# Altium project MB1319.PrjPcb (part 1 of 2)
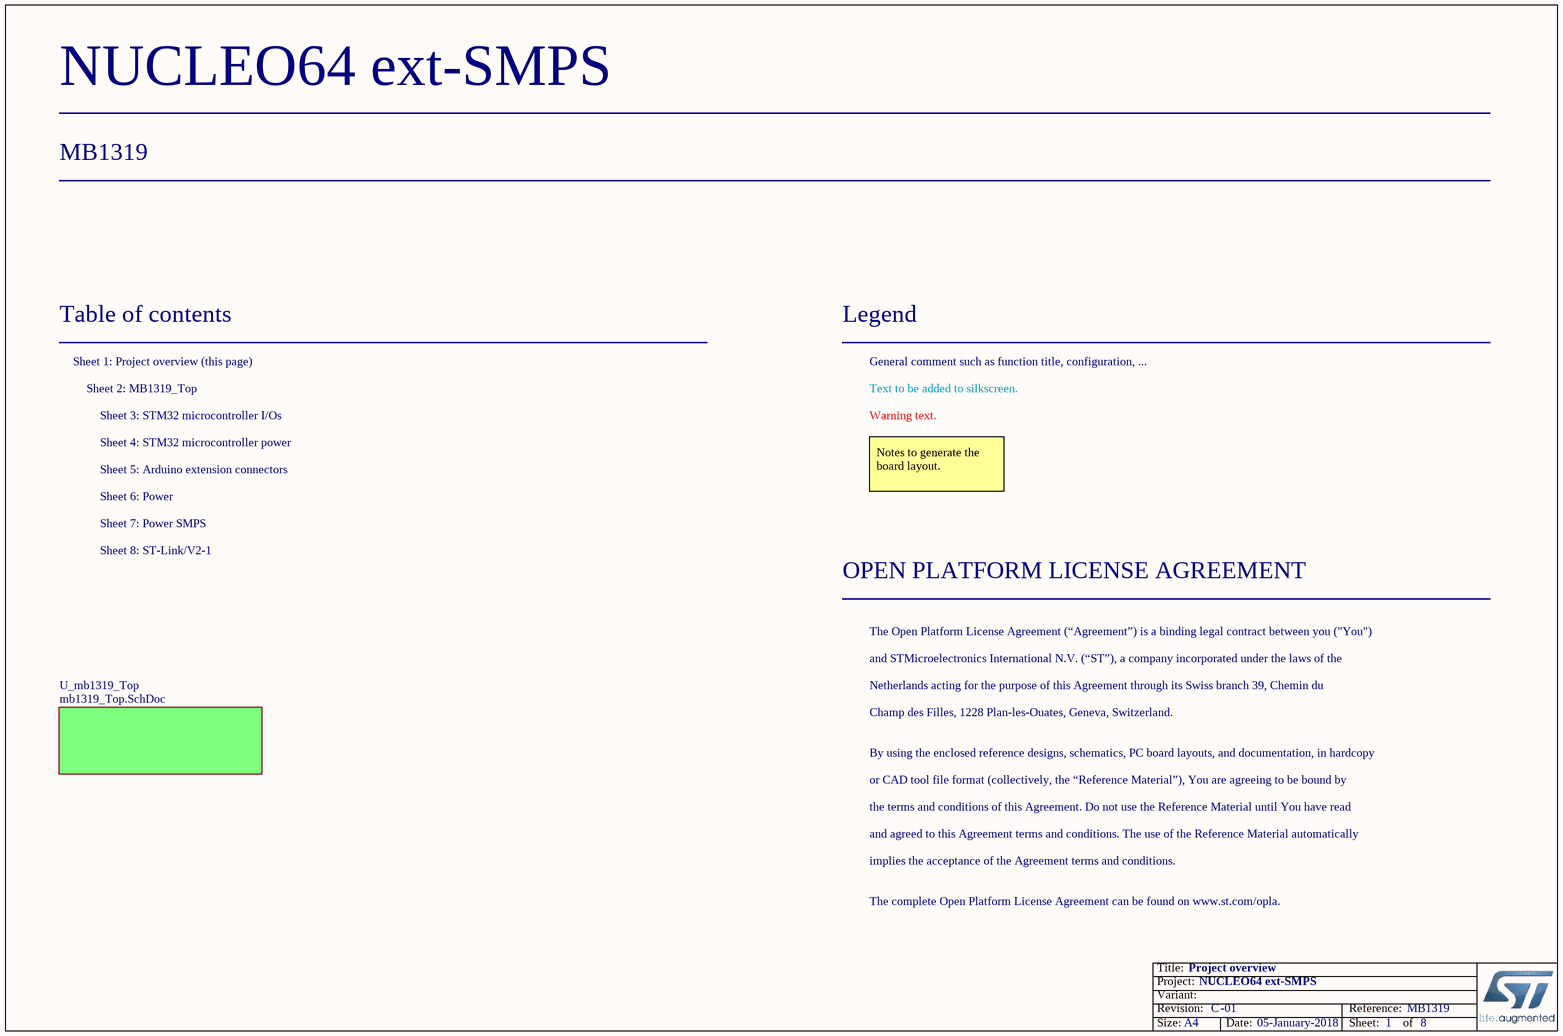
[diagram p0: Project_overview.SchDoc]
Board_Assembly_Revision: 01; Board_Document_Date: 05-January-2018; Board_Name: NUCLEO64 ext-SMPS; Board_PCB_Revision: C; Board_Reference: MB1319
8 sheets, 265 parts. Net scope: flat (ports and power ports of the same name join across sheets).
Board file: MB1319.PcbDoc
Sheets:
  Project_overview.SchDoc
    U_mb1319_Top = MB1319_Top.SchDoc
      U_STM32_microcontroller_IOs = STM32_microcontroller_IOs.SchDoc
      U_STM32_microcontroller_power = STM32_microcontroller_power.SchDoc
      U_Arduino_extension_connectors = Arduino_extension_connectors.SchDoc
      U_Power = Power.SchDoc
      U_Power SMPS = Power SMPS.SchDoc
      U_ST_LINK_V2-1 = ST_LINK_V2-1.SchDoc

## Sheet Project_overview.SchDoc: Project overview
size A4; Date: Not used; ApprovedBy: Not used; CheckedBy: Not used; Author: Not used; CompanyName: STMicroelectronics; DrawnBy: Not used; Engineer: Not used; Organization: Not used; Address1: Not used; Address2: Not used; Address3: Not used; Address4: Not used; DocumentNumber: 1; Revision: Not used; SheetNumber: 1; SheetTotal: 8

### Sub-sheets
U_mb1319_Top = mb1319_Top.SchDoc: no entries

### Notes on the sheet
- Table of contents
- Sheet 1: Project overview (this page)
- Legend
- General comment such as function title, configuration, ...
- Sheet 2: MB1319_Top
- Sheet 4: STM32 microcontroller power
- Sheet 3: STM32 microcontroller I/Os
- Text to be added to silkscreen.
- Warning text.
- Sheet 6: Power
- Sheet 5: Arduino extension connectors
- Notes to generate the board layout.
- Sheet 8: ST-Link/V2-1
- Sheet 7: Power SMPS
- OPEN PLATFORM LICENSE AGREEMENT
- The Open Platform License Agreement (“Agreement”) is a binding legal contract between you ("You")
- and STMicroelectronics International N.V. (“ST”), a company incorporated under the laws of the
- Netherlands acting for the purpose of this Agreement through its Swiss branch 39, Chemin du
- Champ des Filles, 1228 Plan-les-Ouates, Geneva, Switzerland.
- By using the enclosed reference designs, schematics, PC board layouts, and documentation, in hardcopy
- or CAD tool file format (collectively, the “Reference Material”), You are agreeing to be bound by
- the terms and conditions of this Agreement. Do not use the Reference Material until You have read
- and agreed to this Agreement terms and conditions. The use of the Reference Material automatically
- implies the acceptance of the Agreement terms and conditions.
- The complete Open Platform License Agreement can be found on www.st.com/opla.

## Sheet MB1319_Top.SchDoc: mb1319 Top: hierarchical view
size A4; Date: Not used; ApprovedBy: Not used; CheckedBy: Not used; Author: Not used; CompanyName: STMicroelectronics; DrawnBy: Not used; Engineer: Not used; Organization: Not used; Address1: Not used; Address2: Not used; Address3: Not used; Address4: Not used; DocumentNumber: 2; Revision: A-01-P3; SheetNumber: 2; SheetTotal: 8
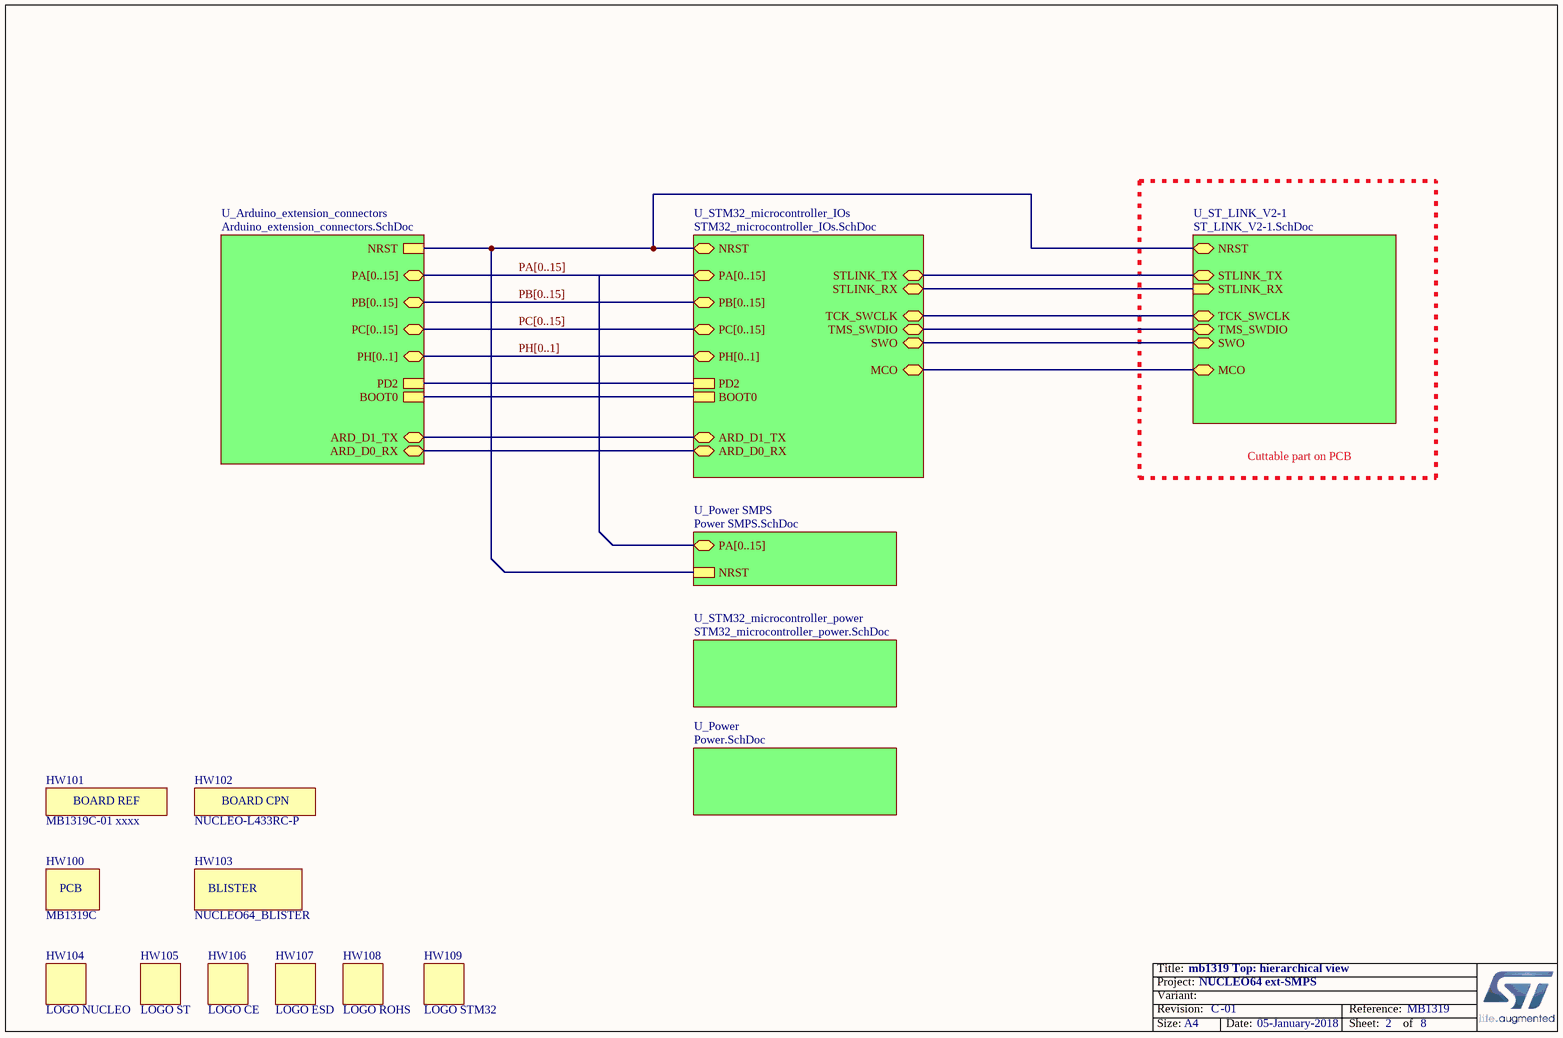
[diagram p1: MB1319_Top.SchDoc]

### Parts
HW100  value MB1319C  (hidden comment: PCB)  (mechanical)
HW101  value MB1319C-01 xxxx  (hidden comment: STICKER_BOARD_REF)  (mechanical)
HW102  value NUCLEO-L433RC-P  (hidden comment: STICKER_BOARD_CPN)  (mechanical)
HW103  value NUCLEO64_BLISTER  [N/A]  (hidden comment: BLISTER)  (mechanical)
HW104  value LOGO NUCLEO  [LOGO_NUCLEO]  (hidden comment: Logo)
HW105  value LOGO ST  [LOGO_STM]  (hidden comment: Logo)
HW106  value LOGO CE  [LOGO_CE]  (hidden comment: Logo)
HW107  value LOGO ESD  [LOGO_MAIN]  (hidden comment: Logo)
HW108  value LOGO ROHS  [LOGO_ROHS]  (hidden comment: Logo)
HW109  value LOGO STM32  [LOGO_STM32]  (hidden comment: Logo)

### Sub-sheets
U_Arduino_extension_connectors = Arduino_extension_connectors.SchDoc: PA[0..15] (bidir), PB[0..15] (bidir), PC[0..15] (bidir), PD2, NRST, BOOT0, PH[0..1] (bidir), ARD_D0_RX, ARD_D1_TX
U_Power = Power.SchDoc: no entries
U_Power SMPS = Power SMPS.SchDoc: PA[0..15] (bidir), NRST
U_ST_LINK_V2-1 = ST_LINK_V2-1.SchDoc: STLINK_TX, TMS_SWDIO, SWO, STLINK_RX (in), MCO, NRST, TCK_SWCLK
U_STM32_microcontroller_IOs = STM32_microcontroller_IOs.SchDoc: PA[0..15] (bidir), PB[0..15] (bidir), PC[0..15] (bidir), PD2, BOOT0, PH[0..1] (bidir), ARD_D0_RX, ARD_D1_TX, NRST, MCO, STLINK_TX, TMS_SWDIO, STLINK_RX, SWO, TCK_SWCLK
U_STM32_microcontroller_power = STM32_microcontroller_power.SchDoc: no entries

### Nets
(unnamed): sheet U_STM32_microcontroller_IOs/PD2, sheet U_Arduino_extension_connectors/PD2
(unnamed): sheet U_STM32_microcontroller_IOs/BOOT0, sheet U_Arduino_extension_connectors/BOOT0  [a separate net that carries the same name]
(unnamed): sheet U_STM32_microcontroller_IOs/ARD_D0_RX, sheet U_Arduino_extension_connectors/ARD_D0_RX  [a separate net that carries the same name]
(unnamed): sheet U_STM32_microcontroller_IOs/ARD_D1_TX, sheet U_Arduino_extension_connectors/ARD_D1_TX  [a separate net that carries the same name]
(unnamed): sheet U_STM32_microcontroller_IOs/NRST, sheet U_Arduino_extension_connectors/NRST, sheet U_Power SMPS/NRST, sheet U_ST_LINK_V2-1/NRST  [a separate net that carries the same name]
(unnamed): sheet U_STM32_microcontroller_IOs/MCO, sheet U_ST_LINK_V2-1/MCO  [a separate net that carries the same name]
(unnamed): sheet U_STM32_microcontroller_IOs/STLINK_TX, sheet U_ST_LINK_V2-1/STLINK_TX  [a separate net that carries the same name]
(unnamed): sheet U_STM32_microcontroller_IOs/TMS_SWDIO, sheet U_ST_LINK_V2-1/TMS_SWDIO  [a separate net that carries the same name]
(unnamed): sheet U_STM32_microcontroller_IOs/STLINK_RX, sheet U_ST_LINK_V2-1/STLINK_RX  [a separate net that carries the same name]
(unnamed): sheet U_STM32_microcontroller_IOs/SWO, sheet U_ST_LINK_V2-1/SWO  [a separate net that carries the same name]
(unnamed): sheet U_STM32_microcontroller_IOs/TCK_SWCLK, sheet U_ST_LINK_V2-1/TCK_SWCLK  [a separate net that carries the same name]

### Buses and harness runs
bus PA[0..15] = sheet U_Arduino_extension_connectors/PA[0..15] = sheet U_Power SMPS/PA[0..15] = sheet U_STM32_microcontroller_IOs/PA[0..15]
bus PB[0..15] = sheet U_Arduino_extension_connectors/PB[0..15] = sheet U_STM32_microcontroller_IOs/PB[0..15]
bus PC[0..15] = sheet U_Arduino_extension_connectors/PC[0..15] = sheet U_STM32_microcontroller_IOs/PC[0..15]
bus PH[0..1] = sheet U_Arduino_extension_connectors/PH[0..1] = sheet U_STM32_microcontroller_IOs/PH[0..1]

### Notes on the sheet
- Cuttable part on PCB

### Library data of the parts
HW100 = MCD-00216: Part_Type: Mechanical; Provided_By: Subcon; Initial_Board_Reference: mb1319
HW101 = MCD-00235: Sticker to mention board reference + serial number; Part_Type: Mechanical; Provided_By: Subcon; Initial_Board_Reference: mb1319
HW102 = MCD-00549: Sticker to mention board CPN code; Part_Type: Mechanical; Provided_By: Subcon; Initial_Board_Reference: mb1319
HW103 = MCD-00037: Part_Type: Mechanical; Provided_By: Subcon; Initial_Board_Reference: mb1274
HW104 = MCD-00636: "NUCLEO" logo footprint for PCB; Part_Type: Mechanical; Initial_Board_Reference: mb1331
HW105 = MCD-00625: "STMicroelectronics" logo footprint for PCB; Part_Type: Mechanical; Initial_Board_Reference: mb1331
HW106 = MCD-00626: "CE" logo footprint for PCB; Part_Type: Mechanical; Initial_Board_Reference: mb1331
HW107 = MCD-00627: "Hand" ESD logo footprint for PCB; Part_Type: Mechanical; Initial_Board_Reference: mb1331
HW108 = MCD-00628: "ROHS" logo footprint for PCB; Part_Type: Mechanical; Initial_Board_Reference: mb1331
HW109 = MCD-00629: "STM32" logo footprint for PCB; Part_Type: Mechanical; Initial_Board_Reference: mb1331

## Sheet STM32_microcontroller_IOs.SchDoc: STM32 microcontroller I/Os
size A4; Date: Not used; ApprovedBy: Not used; CheckedBy: Not used; Author: Not used; CompanyName: STMicroelectronics; DrawnBy: Not used; Engineer: Not used; Organization: Not used; Address1: Not used; Address2: Not used; Address3: Not used; Address4: Not used; DocumentNumber: 3; Revision: Not used; SheetNumber: 3; SheetTotal: 8
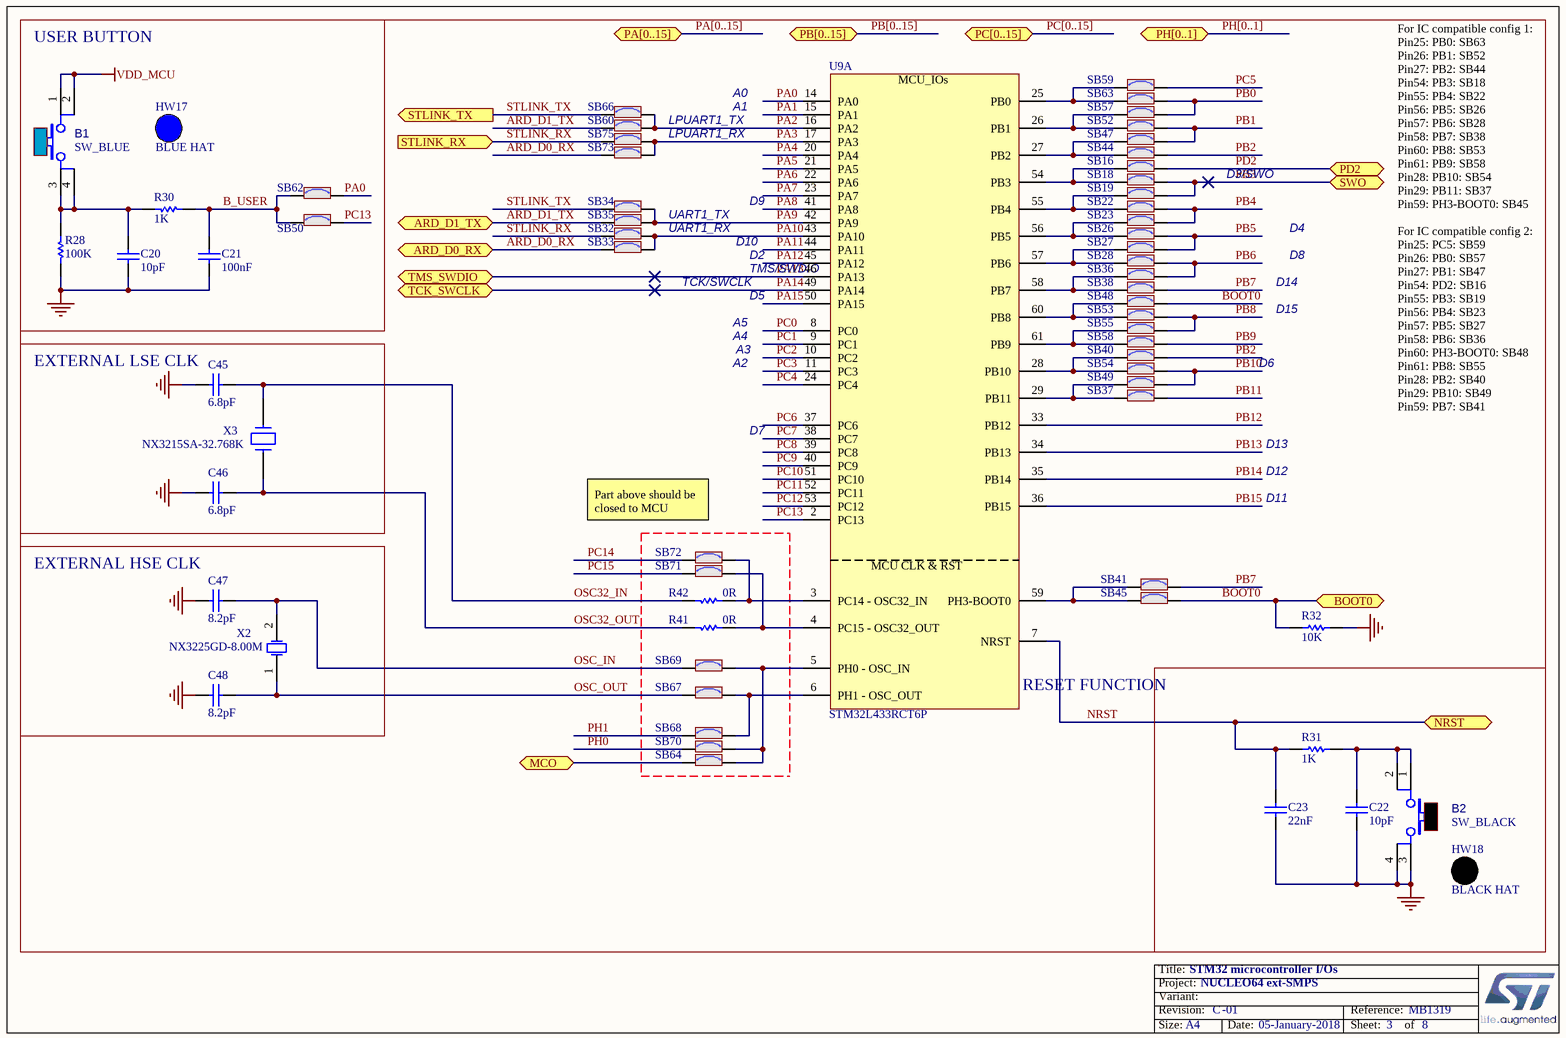
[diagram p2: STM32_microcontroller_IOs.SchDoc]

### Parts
B1  value SW_BLUE  [SWI_WEALTHMETAL_TD-0341_4P_BLUE]  (hidden comment: SW-PUSH-CMS_BLUE)
B2  value SW_BLACK  [SWI_WEALTHMETAL_TD-0341_4P_BLACK]  (hidden comment: SW-PUSH-CMS_BLACK)
C20  value 10pF  [C0603]  (hidden comment: Capacitor)
C21  value 100nF  [C0603]  (hidden comment: Capacitor)
C22  value 10pF  [C0603]  (hidden comment: Capacitor)
C23  value 22nF  [C0603]  (hidden comment: Capacitor)
C45  value 6.8pF  [C0402]  (hidden comment: Capacitor)
C46  value 6.8pF  [C0402]  (hidden comment: Capacitor)
C47  value 8.2pF  [C0402]  (hidden comment: Capacitor)
C48  value 8.2pF  [C0402]  (hidden comment: Capacitor)
HW17  value BLUE HAT  (hidden comment: BUTTON_HAT_BLUE)  (mechanical)
HW18  value BLACK HAT  (hidden comment: BUTTON_HAT_BLACK)  (mechanical)
R28  value 100K  [R0603]  (hidden comment: Resistor)
R30  value 1K  [R0603]  (hidden comment: Resistor)
R31  value 1K  [R0603]  (hidden comment: Resistor)
R32  value 10K  [R0603]  (hidden comment: Resistor)
R41  value 0R  [R0603]  (hidden comment: Resistor)
R42  value 0R  [R0603]  (hidden comment: Resistor)
SB16  SB_ON  [SOLDER-BRIDGE_R0603-0R]  (value not drawn)
SB18  SB_ON  [SOLDER-BRIDGE_R0603-0R]  (value not drawn)
SB19  SB_ON  [SOLDER-BRIDGE_R0603-0R]  (value not drawn)
SB22  SB_ON  [SOLDER-BRIDGE_R0603-0R]  (value not drawn)
SB23  SB_ON  [SOLDER-BRIDGE_R0603-0R]  (value not drawn)
SB26  SB_ON  [SOLDER-BRIDGE_R0603-0R]  (value not drawn)
SB27  SB_ON  [SOLDER-BRIDGE_R0603-0R]  (value not drawn)
SB28  SB_ON  [SOLDER-BRIDGE_R0603-0R]  (value not drawn)
SB32  SB_ON  [SOLDER-BRIDGE_R0603-0R]  (value not drawn)
SB33  SB_ON  [SOLDER-BRIDGE_R0603-0R]  (value not drawn)
SB34  SB_ON  [SOLDER-BRIDGE_R0603-0R]  (value not drawn)
SB35  SB_ON  [SOLDER-BRIDGE_R0603-0R]  (value not drawn)
SB36  SB_ON  [SOLDER-BRIDGE_R0603-0R]  (value not drawn)
SB37  SB_ON  [SOLDER-BRIDGE_R0603-0R]  (value not drawn)
SB38  SB_ON  [SOLDER-BRIDGE_R0603-0R]  (value not drawn)
SB40  SB_ON  [SOLDER-BRIDGE_R0603-0R]  (value not drawn)
SB41  SB_ON  [SOLDER-BRIDGE_R0603-0R]  (value not drawn)
SB44  SB_ON  [SOLDER-BRIDGE_R0603-0R]  (value not drawn)
SB45  SB_ON  [SOLDER-BRIDGE_R0603-0R]  (value not drawn)
SB47  SB_ON  [SOLDER-BRIDGE_R0603-0R]  (value not drawn)
SB48  SB_ON  [SOLDER-BRIDGE_R0603-0R]  (value not drawn)
SB49  SB_ON  [SOLDER-BRIDGE_R0603-0R]  (value not drawn)
SB50  SB_ON  [SOLDER-BRIDGE_R0603-0R]  (value not drawn)
SB52  SB_ON  [SOLDER-BRIDGE_R0603-0R]  (value not drawn)
SB53  SB_ON  [SOLDER-BRIDGE_R0603-0R]  (value not drawn)
SB54  SB_ON  [SOLDER-BRIDGE_R0603-0R]  (value not drawn)
SB55  SB_ON  [SOLDER-BRIDGE_R0603-0R]  (value not drawn)
SB57  SB_ON  [SOLDER-BRIDGE_R0603-0R]  (value not drawn)
SB58  SB_ON  [SOLDER-BRIDGE_R0603-0R]  (value not drawn)
SB59  SB_ON  [SOLDER-BRIDGE_R0603-0R]  (value not drawn)
SB60  SB_ON  [SOLDER-BRIDGE_R0603-0R]  (value not drawn)
SB62  SB_ON  [SOLDER-BRIDGE_R0603-0R]  (value not drawn)
SB63  SB_ON  [SOLDER-BRIDGE_R0603-0R]  (value not drawn)
SB64  SB_ON  [SOLDER-BRIDGE_R0603-0R]  (value not drawn)
SB66  SB_ON  [SOLDER-BRIDGE_R0603-0R]  (value not drawn)
SB67  SB_ON  [SOLDER-BRIDGE_R0603-0R]  (value not drawn)
SB68  SB_ON  [SOLDER-BRIDGE_R0603-0R]  (value not drawn)
SB69  SB_ON  [SOLDER-BRIDGE_R0603-0R]  (value not drawn)
SB70  SB_ON  [SOLDER-BRIDGE_R0603-0R]  (value not drawn)
SB71  SB_ON  [SOLDER-BRIDGE_R0603-0R]  (value not drawn)
SB72  SB_ON  [SOLDER-BRIDGE_R0603-0R]  (value not drawn)
SB73  SB_ON  [SOLDER-BRIDGE_R0603-0R]  (value not drawn)
SB75  SB_ON  [SOLDER-BRIDGE_R0603-0R]  (value not drawn)
U9  STM32L433RCT6P  [ICC_LQFP64_10X10_P050_SOCKET_YAMAICHI_IC149-064-069-B5_NM]  (part A of 2)
X2  value NX3225GD-8.00M  [CRY_NX3225GD_2P]  (hidden comment: XTAL_8M_NX3225GD)
X3  value NX3215SA-32.768K  [CRY_NX3215SA_2P]  (hidden comment: XTAL_32K_NX3215SA)

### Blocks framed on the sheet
USER BUTTON: B1 C20 C21 HW17 R28 R30 SB50 SB62
EXTERNAL LSE CLK: C45 C46 X3
EXTERNAL HSE CLK: C47 C48 X2
RESET FUNCTION: B2 C22 C23 HW18 R31

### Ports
ARD_D0_RX, ARD_D1_TX, BOOT0, MCO, NRST, PA[0..15] (bidir), PB[0..15] (bidir), PC[0..15] (bidir), PD2, PH[0..1] (bidir), STLINK_RX (in), STLINK_TX (out), SWO, TCK_SWCLK, TMS_SWDIO

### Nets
GND: B2.3 B2.4 C20.1 C21.1 C22.1 C23.1 C45.2 C46.2 C47.1 C48.1 R28.1 R32.1
VDD_MCU: B1.1 B1.2
ARD_D0_RX: SB33.2 SB73.2 ; port ARD_D0_RX
ARD_D1_TX: SB35.2 SB60.2 ; port ARD_D1_TX
B_USER: C21.2 R30.1 SB50.1 SB62.1
BOOT0: R32.2 SB45.2 SB48.2 ; port BOOT0
MCO: SB64.1 ; port MCO
NRST: C23.2 R31.1 U9.7(NRST) ; port NRST
OSC32_IN: C45.1 R42.2 X3.1
OSC32_OUT: C46.1 R41.2 X3.2
OSC_IN: C47.2 SB69.1 X2.2(OSC2)
OSC_OUT: C48.2 SB67.1 X2.1(OSC1)
PA0: SB62.2 U9.14(PA0)
PA1: U9.15(PA1)
PA2: SB60.1 SB66.2 U9.16(PA2)
PA3: SB73.1 SB75.2 U9.17(PA3)
PA4: U9.20(PA4)
PA5: U9.21(PA5)
PA6: U9.22(PA6)
PA7: U9.23(PA7)
PA8: U9.41(PA8)
PA9: SB34.2 SB35.1 U9.42(PA9)
PA10: SB32.2 SB33.1 U9.43(PA10)
PA11: U9.44(PA11)
PA12: U9.45(PA12)
PA13: U9.46(PA13) ; port TMS_SWDIO
PA14: U9.49(PA14) ; port TCK_SWCLK
PA15: U9.50(PA15)
PB0: SB57.2 SB63.2
PB1: SB47.2 SB52.2
PB2: SB40.2 SB44.2
PB3: SB18.2 SB19.2 ; port SWO
PB4: SB22.2 SB23.2
PB5: SB26.2 SB27.2
PB6: SB28.2 SB36.2
PB7: SB38.2 SB41.1
PB8: SB53.2 SB55.2
PB9: SB58.2
PB10: SB49.2 SB54.2
PB11: SB37.2
PB12: U9.33(PB12)
PB13: U9.34(PB13)
PB14: U9.35(PB14)
PB15: U9.36(PB15)
PC0: U9.8(PC0)
PC1: U9.9(PC1)
PC2: U9.10(PC2)
PC3: U9.11(PC3)
PC4: U9.24(PC4)
PC5: SB59.2
PC6: U9.37(PC6)
PC7: U9.38(PC7)
PC8: U9.39(PC8)
PC9: U9.40(PC9)
PC10: U9.51(PC10)
PC11: U9.52(PC11)
PC12: U9.53(PC12)
PC13: SB50.2 U9.2(PC13)
PC14: SB72.1
PC15: SB71.1
PD2: SB16.2 ; port PD2
PH0: SB70.1
PH1: SB68.1
STLINK_RX: SB32.1 SB75.1 ; port STLINK_RX
STLINK_TX: SB34.1 SB66.1 ; port STLINK_TX
NetB1_3: B1.3 B1.4 C20.2 R28.2 R30.2
NetB2_1: B2.1 B2.2 C22.2 R31.2
NetR41_1: R41.1 SB71.2 U9.4(PC15_-_OSC32_OUT)
NetR42_1: R42.1 SB72.2 U9.3(PC14_-_OSC32_IN)
NetSB16_1: SB16.1 SB18.1 U9.54(PB3)
NetSB19_1: SB19.1 SB22.1 U9.55(PB4)
NetSB23_1: SB23.1 SB26.1 U9.56(PB5)
NetSB27_1: SB27.1 SB28.1 U9.57(PB6)
NetSB36_1: SB36.1 SB38.1 U9.58(PB7)
NetSB37_1: SB37.1 SB49.1 U9.29(PB11)
NetSB40_1: SB40.1 SB54.1 U9.28(PB10)
NetSB41_2: SB41.2 SB45.1 U9.59(PH3-BOOT0)
NetSB44_1: SB44.1 SB47.1 U9.27(PB2)
NetSB48_1: SB48.1 SB53.1 U9.60(PB8)
NetSB52_1: SB52.1 SB57.1 U9.26(PB1)
NetSB55_1: SB55.1 SB58.1 U9.61(PB9)
NetSB59_1: SB59.1 SB63.1 U9.25(PB0)
NetSB64_2: SB64.2 SB69.2 SB70.2 U9.5(PH0_-_OSC_IN)
NetSB67_2: SB67.2 SB68.2 U9.6(PH1_-_OSC_OUT)

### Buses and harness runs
bus PA[0..15] = port PA[0..15]
bus PB[0..15] = port PB[0..15]
bus PC[0..15] = port PC[0..15]
bus PH[0..1] = port PH[0..1]

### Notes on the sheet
- A0
- A1
- LPUART1_TX
- LPUART1_RX
- D3/SWO
- UART1_RX
- UART1_TX
- D10
- D9
- D4
- For IC compatible config 1:
  Pin25: PB0: SB63
  Pin26: PB1: SB52
  Pin27: PB2: SB44
  Pin54: PB3: SB18
  Pin55: PB4: SB22
  Pin56: PB5: SB26
  Pin57: PB6: SB28
  Pin58: PB7: SB38
  Pin60: PB8: SB53
  Pin61: PB9: SB58
  Pin28: PB10: SB54
  Pin29: PB11: SB37
  Pin59: PH3-BOOT0: SB45
- TCK/SWCLK
- D2
- D5
- TMS/SWDIO
- D14
- D15
- D8
- A3
- A2
- A4
- A5
- D6
- D7
- D13
- For IC compatible config 2:
  Pin25: PC5: SB59
  Pin26: PB0: SB57
  Pin27: PB1: SB47
  Pin54: PD2: SB16
  Pin55: PB3: SB19
  Pin56: PB4: SB23
  Pin57: PB5: SB27
  Pin58: PB6: SB36
  Pin60: PH3-BOOT0: SB48
  Pin61: PB8: SB55
  Pin28: PB2: SB40
  Pin29: PB10: SB49
  Pin59: PB7: SB41
- Part above should be closed to MCU
- D12
- D11

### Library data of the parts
B1 = MCD-00002: Non-Open Push-Button 0.1A 24V; Manufacturer_Part_Number: TD0341X-G01-BLU; Manufacturer: WEALTHMETAL; Alternate_Manufacturer_Part_Number: 535-930; Alternate_Manufacturer: FARNELL; Part_Type: Misc; Provided_By: Subcon; Initial_Board_Reference: mb1274
B2 = MCD-00001: Non-Open Push-Button 0.1A 24V; Manufacturer_Part_Number: TD0341X-G01-BLA; Manufacturer: WEALTHMETAL; Alternate_Manufacturer_Part_Number: 535-930; Alternate_Manufacturer: FARNELL; Part_Type: Misc; Provided_By: Subcon; Initial_Board_Reference: mb1274
C20 C22 = MCD-00637: Capacitor,10pF,50V,NPO,5%,0603; Manufacturer_Part_Number: CC0603JRNPO9BN100; Manufacturer: YAGEO; Provided_By: subcon; Initial_Board_Reference: mb1319
C21 = MCD-00237: Capacitor,100nF,6V3,X5R,10%,0603; Manufacturer_Part_Number: CC0603KRX5R5BB104; Manufacturer: YAGEO; Provided_By: Subcon; Initial_Board_Reference: mb1319
C23 = MCD-00555: Capacitor,22nF,10%,25V,X7R,0603; Manufacturer_Part_Number: CC0603KRX7R8BB223; Manufacturer: YAGEO; Provided_By: Subcon; Initial_Board_Reference: mb1331
C45 C46 = MCD-00674: Capacitor, MLCC, 6.8pF, 50V, NPO, +-0.25pF, 0402, T=0.5mm; Manufacturer_Part_Number: CC0402CRNPO9BN6R8; Manufacturer: YAGEO; Provided_By: Subcon; Initial_Board_Reference: mb1319
C47 C48 = MCD-00004: Capacitor,8.2pF,50V,NPO,4%,0402; Manufacturer_Part_Number: 04025A8R2CAT2A; Manufacturer: AVX; Provided_By: Subcon; Initial_Board_Reference: mb1274
HW17 = MCD-00634: Blue Hat for switch TD0341X-G01-BLU; Part_Type: Mechanical; Manufacturer_Part_Number: 988.16.09.3.00002_SH-517; Manufacturer: JIUBABA; Provided_By: Subcon; Initial_Board_Reference: mb1319
HW18 = MCD-00635: Black Hat for switch TD0341X-G01-BLA; Part_Type: Mechanical; Manufacturer_Part_Number: 988.16.09.3.00003_SH-517; Manufacturer: JIUBABA; Provided_By: Subcon; Initial_Board_Reference: mb1319
R28 = MCD-00223: Resistor,100K,0603,1%,1/10W; Manufacturer_Part_Number: RC0603FR-07100KL; Manufacturer: YAGEO; Provided_By: Subcon; Initial_Board_Reference: mb1319
R30 R31 = MCD-00070: Resistor,1K,0603,1%,1/10W; Manufacturer_Part_Number: RC0603FR-071KL; Manufacturer: YAGEO; Provided_By: Subcon; Initial_Board_Reference: mb1274
R32 = MCD-00220: Resistor,10K,0603,1%,1/10W; Manufacturer_Part_Number: RC0603FR-0710KL; Manufacturer: YAGEO; Provided_By: Subcon; Initial_Board_Reference: mb1319
R41 R42 = MCD-00056: Resistor,0R,0603,5%,1/10W; Manufacturer_Part_Number: RC0603JR-070RL; Manufacturer: YAGEO; Provided_By: subcon; Initial_Board_Reference: mb1274
SB16 SB18 SB19 SB22 SB23 SB26-SB28 SB32-SB38 SB40 SB41 SB44 SB45 SB47-SB50 SB52-SB55 SB57-SB60 SB62-SB64 SB66-SB73 SB75 = MCD-00071: Solder Bridge ON; Part_Type: Mechanical; Provided_By: Subcon; Initial_Board_Reference: mb1274
U9 = MCD-00548: Little ORCA 256_STM32L433P External SMPS configuration. LQFP64 package; Part_Type: IC; Manufacturer: STMICROELECTRONICS; ECCN_US: 3A991A2; ECCN_EU: NEC; Provided_By: STM; Initial_Board_Reference: mb1319
X2 = MCD-00092: Crystal 8Mhz, 8pF, -+50PPM, SMD; Manufacturer_Part_Number: NX3225GD 8MHz EXS00A-CG04874; Manufacturer: NDK; Part_Type: Crystal_Osc; ECCN_US: EAR99; ECCN_EU: NEC; Provided_By: STM; Initial_Board_Reference: mb1274
X3 = MCD-00091: Crystal 32.768kHz, 6pF, -+20PPM, R=50K, SMD; Manufacturer_Part_Number: NX3215SA 32.768KHz EXS00A-MU00525; Manufacturer: NDK; Part_Type: Crystal_Osc; ECCN_US: EAR99; ECCN_EU: NEC; Provided_By: STM; Initial_Board_Reference: mb1274

## Sheet STM32_microcontroller_power.SchDoc: STM32 microcontroller Power
size A4; Date: Not used; ApprovedBy: Not used; CheckedBy: Not used; Author: Not used; CompanyName: STMicroelectronics; DrawnBy: Not used; Engineer: Not used; Organization: Not used; Address1: Not used; Address2: Not used; Address3: Not used; Address4: Not used; DocumentNumber: 4; Revision: Not used; SheetNumber: 4; SheetTotal: 8
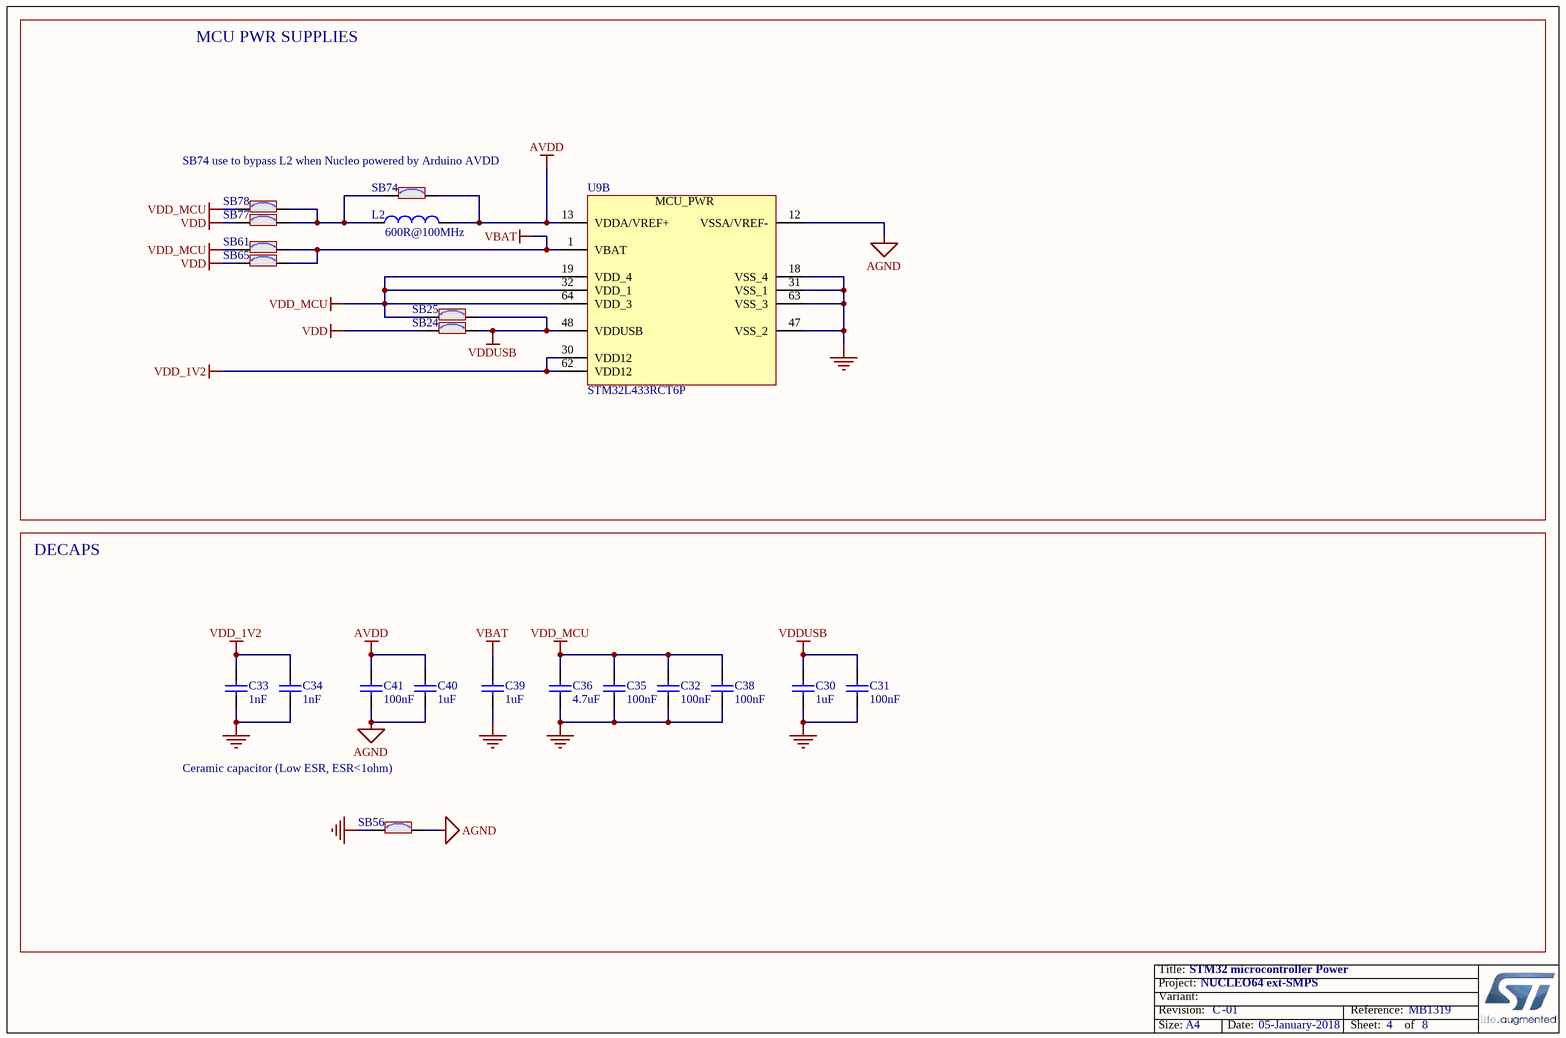
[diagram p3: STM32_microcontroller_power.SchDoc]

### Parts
C30  value 1uF  [C0603]  (hidden comment: Capacitor)
C31  value 100nF  [C0603]  (hidden comment: Capacitor)
C32  value 100nF  [C0603]  (hidden comment: Capacitor)
C33  value 1nF  [C0603]  (hidden comment: Capacitor)
C34  value 1nF  [C0603]  (hidden comment: Capacitor)
C35  value 100nF  [C0603]  (hidden comment: Capacitor)
C36  value 4.7uF  [C0603]  (hidden comment: Capacitor)
C38  value 100nF  [C0603]  (hidden comment: Capacitor)
C39  value 1uF  [C0603]  (hidden comment: Capacitor)
C40  value 1uF  [C0603]  (hidden comment: Capacitor)
C41  value 100nF  [C0603]  (hidden comment: Capacitor)
L2  value 600R@100MHz  [L0603]  (hidden comment: BEAD)
SB24  SB_ON  [SOLDER-BRIDGE_R0603-0R]  (value not drawn)
SB25  SB_ON  [SOLDER-BRIDGE_R0603-0R]  (value not drawn)
SB56  SB_ON  [SOLDER-BRIDGE_R0603-0R]  (value not drawn)
SB61  SB_ON  [SOLDER-BRIDGE_R0603-0R]  (value not drawn)
SB65  SB_ON  [SOLDER-BRIDGE_R0603-0R]  (value not drawn)
SB74  SB_ON  [SOLDER-BRIDGE_R0603-0R]  (value not drawn)
SB77  SB_ON  [SOLDER-BRIDGE_R0603-0R]  (value not drawn)
SB78  SB_ON  [SOLDER-BRIDGE_R0603-0R]  (value not drawn)
U9  STM32L433RCT6P  (part B of 2)

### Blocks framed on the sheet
MCU PWR SUPPLIES: L2 SB24 SB25 SB61 SB65 SB74 SB77 SB78 U9
DECAPS: C30-C36 C38-C41 SB56

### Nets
AGND: C40.2 C41.1 SB56.2 U9.12(VSSA/VREF-)
AVDD: C40.1 C41.2 L2.2 SB74.2 U9.13(VDDA/VREF+)
GND: C30.2 C31.1 C32.1 C33.1 C34.1 C35.1 C36.1 C38.1 C39.2 SB56.1 U9.18(VSS_4) U9.31(VSS_1) U9.47(VSS_2) U9.63(VSS_3)
VBAT: C39.1 SB61.1 SB65.1 U9.1(VBAT)
VDD: SB24.1 SB65.2 SB77.1
VDD_1V2: C33.2 C34.2 U9.30(VDD12) U9.62(VDD12)
VDD_MCU: C32.2 C35.2 C36.2 C38.2 SB25.1 SB61.2 SB78.1 U9.19(VDD_4) U9.32(VDD_1) U9.64(VDD_3)
VDDUSB: C30.1 C31.2 SB24.2 SB25.2 U9.48(VDDUSB)
NetL2_1: L2.1 SB74.1 SB77.2 SB78.2

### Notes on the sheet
- SB74 use to bypass L2 when Nucleo powered by Arduino AVDD
- Ceramic capacitor (Low ESR, ESR<1ohm)

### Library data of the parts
C30 C39 C40 = MCD-00238: Capacitor,1uF,6V3,X5R,10%,0603; Manufacturer_Part_Number: CC0603KRX5R5BB105; Manufacturer: YAGEO; Provided_By: Subcon; Initial_Board_Reference: mb1319
C31 C32 C35 C38 C41 = MCD-00237: as C21 on sheet STM32_microcontroller_IOs
C33 C34 = MCD-00273: Capacitor,1nF,16V,X7R,10%,0603; Manufacturer_Part_Number: CC0603KRX7R7BB102; Manufacturer: YAGEO; Provided_By: Subcon; Initial_Board_Reference: mb1319
C36 = MCD-00009: Capacitor,4.7uF,16V, X5R,10%,0603; Manufacturer_Part_Number: CC0603KRX5R7BB475; Manufacturer: YAGEO; Provided_By: subcon; Initial_Board_Reference: mb1274
L2 = MCD-00047: SMD Chip ferrite bead, 600R@100MHz +/-25%, 350mA, 500mohm DC, 0603, T=0.8mm; Part_Type: Inductor; Manufacturer_Part_Number: FCM1608KF-601T03; Manufacturer: TAI-TECH; Provided_By: Subcon; Initial_Board_Reference: mb1274
SB24 SB25 SB56 SB61 SB65 SB74 SB77 SB78 = MCD-00071: as SB16 on sheet STM32_microcontroller_IOs
U9 = MCD-00548: as U9 on sheet STM32_microcontroller_IOs

## Sheet Arduino_extension_connectors.SchDoc: Arduino extension connectors
size A4; Date: Not used; ApprovedBy: Not used; CheckedBy: Not used; Author: Not used; CompanyName: STMicroelectronics; DrawnBy: Not used; Engineer: Not used; Organization: Not used; Address1: Not used; Address2: Not used; Address3: Not used; Address4: Not used; DocumentNumber: 5; Revision: Not used; SheetNumber: 5; SheetTotal: 8
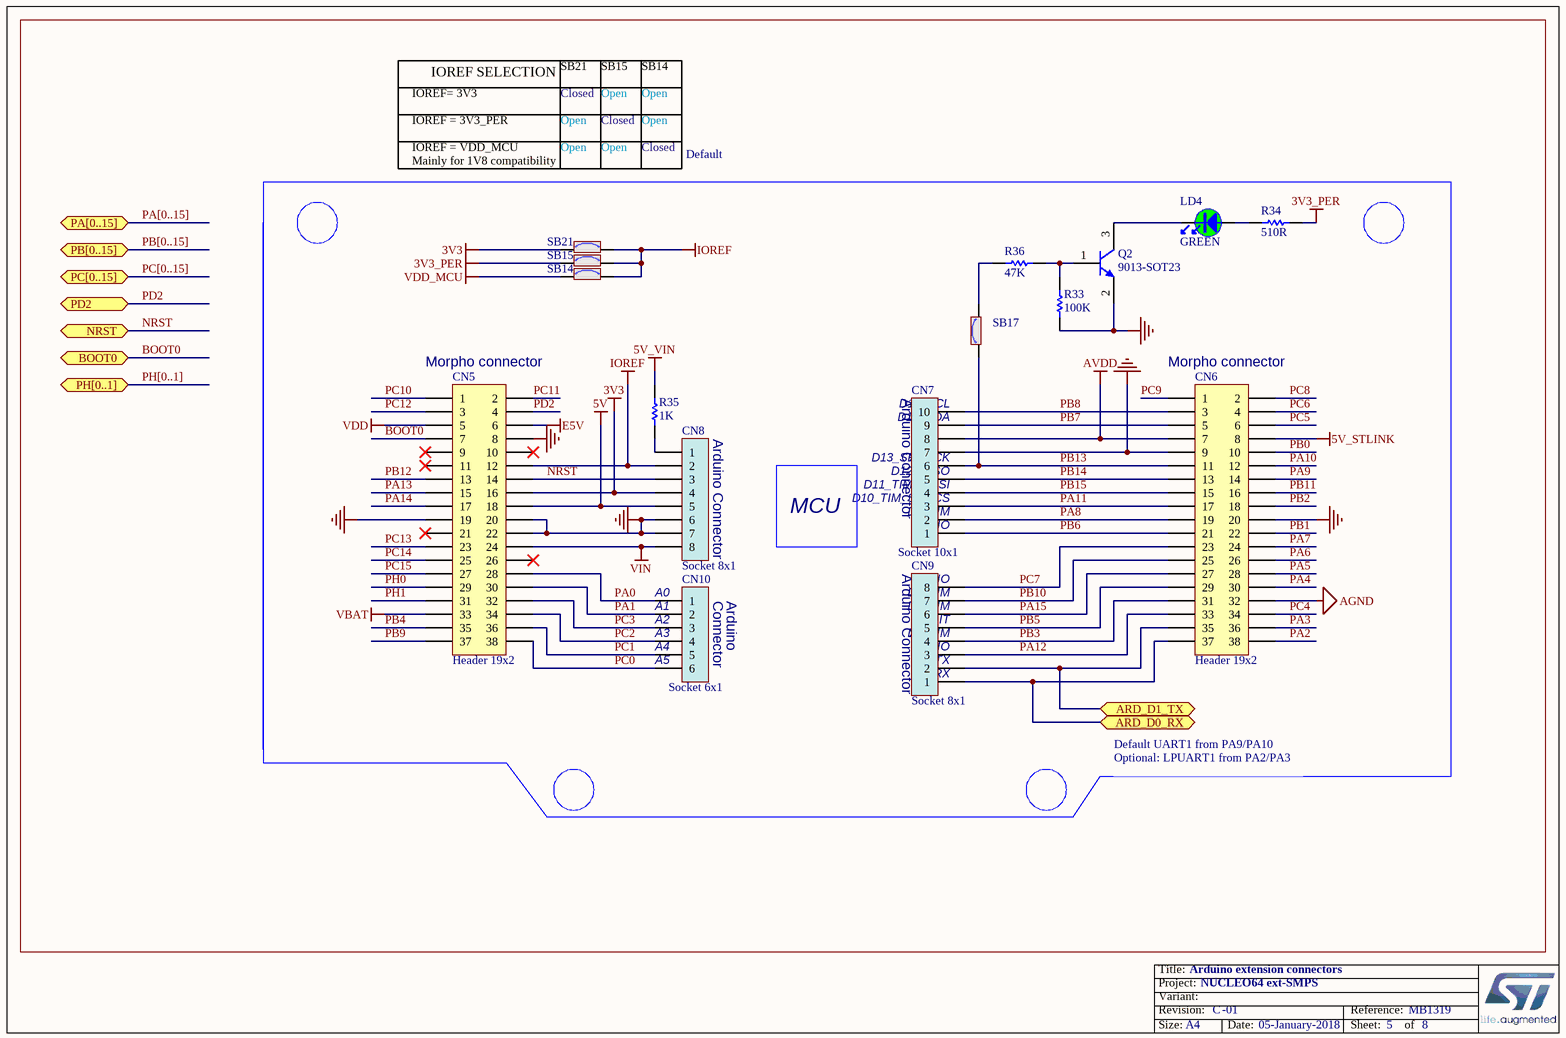
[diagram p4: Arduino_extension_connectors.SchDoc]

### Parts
CN5  Header 19x2  [CON_SAMTEC_TSW-119-09-X-D]
CN6  Header 19x2  [CON_SAMTEC_TSW-119-09-X-D]
CN7  Socket 10x1  [CON_SAMTEC_SSW-110-03-X-S]
CN8  Socket 8x1  [CON_SAMTEC_SSW-108-03-X-S]
CN9  Socket 8x1  [CON_SAMTEC_SSW-108-03-X-S]
CN10  Socket 6x1  [CON_SAMTEC_SSW-106-03-X-S]
LD4  value GREEN  [LED_0603_GREEN]  (hidden comment: LED_green)
Q2  9013-SOT23  [NPN_SOT23]
R33  value 100K  [R0603]  (hidden comment: Resistor)
R34  value 510R  [R0603]  (hidden comment: Resistor)
R35  value 1K  [R0603]  (hidden comment: Resistor)
R36  value 47K  [R0603]  (hidden comment: Resistor)
SB14  SB_ON  [SOLDER-BRIDGE_R0603-0R]  (value not drawn)
SB15  SB_ON  [SOLDER-BRIDGE_R0603-0R]  (value not drawn)
SB17  SB_ON  [SOLDER-BRIDGE_R0603-0R]  (value not drawn)
SB21  SB_ON  [SOLDER-BRIDGE_R0603-0R]  (value not drawn)

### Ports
ARD_D0_RX, ARD_D1_TX, BOOT0, NRST, PA[0..15] (bidir), PB[0..15] (bidir), PC[0..15] (bidir), PD2, PH[0..1] (bidir)

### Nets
3V3: CN5.16 CN8.4 SB21.2
3V3_PER: R34.1 SB15.2
5V: CN5.18 CN8.5
5V_STLINK: CN6.8
5V_VIN: R35.2
AGND: CN6.32
AVDD: CN6.7 CN7.8
E5V: CN5.6
GND: CN5.8 CN5.19 CN5.20 CN5.22 CN6.9 CN6.20 CN7.7 CN8.6 CN8.7 Q2.2(E) R33.1
IOREF: CN5.12 CN8.2 SB14.1 SB15.1 SB21.1
VBAT: CN5.33
VDD: CN5.5
VDD_MCU: SB14.2
VIN: CN5.24 CN8.8
ARD_D0_RX: CN6.37 CN9.1 ; port ARD_D0_RX
ARD_D1_TX: CN6.35 CN9.2 ; port ARD_D1_TX
BOOT0: CN5.7 ; port BOOT0
NRST: CN5.14 CN8.3 ; port NRST
PA0: CN5.28 CN10.1
PA1: CN5.30 CN10.2
PA2: CN6.38
PA3: CN6.36
PA4: CN6.30
PA5: CN6.28
PA6: CN6.26
PA7: CN6.24
PA8: CN6.19 CN7.2
PA9: CN6.14
PA10: CN6.12
PA11: CN6.17 CN7.3
PA12: CN6.33 CN9.3
PA13: CN5.15
PA14: CN5.17
PA15: CN6.27 CN9.6
PB0: CN6.10
PB1: CN6.22
PB2: CN6.18
PB3: CN6.31 CN9.4
PB4: CN5.35
PB5: CN6.29 CN9.5
PB6: CN6.21 CN7.1
PB7: CN6.5 CN7.9
PB8: CN6.3 CN7.10
PB9: CN5.37
PB10: CN6.25 CN9.7
PB11: CN6.16
PB12: CN5.13
PB13: CN6.11 CN7.6 SB17.1
PB14: CN6.13 CN7.5
PB15: CN6.15 CN7.4
PC0: CN5.38 CN10.6
PC1: CN5.36 CN10.5
PC2: CN5.34 CN10.4
PC3: CN5.32 CN10.3
PC4: CN6.34
PC5: CN6.6
PC6: CN6.4
PC7: CN6.23 CN9.8
PC8: CN6.2
PC9: CN6.1
PC10: CN5.1
PC11: CN5.2
PC12: CN5.3
PC13: CN5.23
PC14: CN5.25
PC15: CN5.27
PD2: CN5.4 ; port PD2
PH0: CN5.29
PH1: CN5.31
NetCN8_1: CN8.1 R35.1
NetLD4_1: LD4.1 R34.2
NetLD4_2: LD4.2 Q2.3(C)
NetQ2_1: Q2.1(B) R33.2 R36.2
NetR36_1: R36.1 SB17.2

Not connected (* = marked no-connect by the designer): CN5 9* 10* 11* 21* 26*

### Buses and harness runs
bus PA[0..15] = port PA[0..15]
bus PB[0..15] = port PB[0..15]
bus PC[0..15] = port PC[0..15]
bus PH[0..1] = port PH[0..1]

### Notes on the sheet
- IOREF= 3V3
- IOREF SELECTION
- SB21
- Closed
- SB15
- Open
- SB14
- IOREF = 3V3_PER
- IOREF = VDD_MCU
- Mainly for 1V8 compatibility
- Default
- (near CN5) Morpho connector
- (near CN6) Morpho connector
- (near CN8) Arduino Connector
- (near CN7) Arduino Connector
- (near CN7) D14_SDA
- (near CN7) D15_SCL
- MCU
- (near CN7) D9_TIM
- (near CN7) D10_TIM_SPI_CS
- (near CN7) D13_SPI_SCK
- (near CN7) D12_MISO
- (near CN7) D11_TIM_MOSI
- (near CN9) Arduino Connector
- (near CN9) D7_IO
- (near CN7) D8_IO
- (near CN10) A0
- (near CN10) A1
- (near CN10) A2
- (near CN10) A3
- (near CN10) A4
- (near CN10) Connector
- (near CN10) Arduino
- (near CN9) D2_IO
- (near CN9) D4_IT
- (near CN9) D3_TIM
- (near CN9) D5_TIM
- (near CN9) D6_TIM
- (near CN10) A5
- (near CN9) D0_RX
- (near CN9) D1_TX
- Default UART1 from PA9/PA10
  Optional: LPUART1 from PA2/PA3

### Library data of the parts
CN5 CN6 = MCD-00213: Header, 19x2, 2,54mm, VR, TH, Height 5.84mm/2.54mm; Manufacturer_Part_Number: TSW-119-09-x-D; Manufacturer: SAMTEC; Part_Type: Connector; Provided_By: Subcon; Initial_Board_Reference: mb1319
CN7 = MCD-00262: Socket, 10x1, 2.54mm, VR, TH, Height 8.51mm/10mm; Manufacturer_Part_Number: SSW-110-03-x-S; Manufacturer: SAMTEC; Part_Type: Connector; Provided_By: Subcon; Initial_Board_Reference: mb1319
CN8 CN9 = MCD-00261: Socket, 8x1, 2.54mm, VR, TH, Height 8.51mm/10mm; Manufacturer_Part_Number: SSW-108-03-x-S; Manufacturer: SAMTEC; Part_Type: Connector; Provided_By: Subcon; Initial_Board_Reference: mb1319
CN10 = MCD-00260: Socket, 6x1, 2.54mm, VR, TH, Height 8.51mm/10mm; Manufacturer_Part_Number: SSW-106-03-x-S; Manufacturer: SAMTEC; Part_Type: Connector; Provided_By: Subcon; Initial_Board_Reference: mb1319
LD4 = MCD-00050: LED, Green, 0603; Manufacturer_Part_Number: 19-213SYGC/S530-E2/TR8; Manufacturer: EVERLIGHT; Part_Type: Display; ECCN_US: EAR99; ECCN_EU: NEC; Provided_By: Subcon; Initial_Board_Reference: mb1274
Q2 = MCD-00073: NPN Bipolar Transistor; Part_Type: IC; Manufacturer_Part_Number: BSR14; Manufacturer: NXP; ECCN_US: EAR99; ECCN_EU: NEC; Provided_By: Subcon; Initial_Board_Reference: mb1274
R33 = MCD-00223: as R28 on sheet STM32_microcontroller_IOs
R34 = MCD-00225: Resistor,510R,0603,1%,1/10W; Manufacturer_Part_Number: RC0603FR-07510RL; Manufacturer: YAGEO; Provided_By: Subcon; Initial_Board_Reference: mb1319
R35 = MCD-00070: as R30 on sheet STM32_microcontroller_IOs
R36 = MCD-00222: Resistor,47K,0603,1%,1/10W; Manufacturer_Part_Number: RC0603FR-0747KL; Manufacturer: YAGEO; Provided_By: Subcon; Initial_Board_Reference: mb1319
SB14 SB15 SB17 SB21 = MCD-00071: as SB16 on sheet STM32_microcontroller_IOs

## Sheet Power.SchDoc: MAIN POWER 5V / 3V3
size A4; Date: Not used; ApprovedBy: Not used; CheckedBy: Not used; Author: Not used; CompanyName: STMicroelectronics; DrawnBy: Not used; Engineer: Not used; Organization: Not used; Address1: Not used; Address2: Not used; Address3: Not used; Address4: Not used; DocumentNumber: 6; Revision: Not used; SheetNumber: 6; SheetTotal: 8
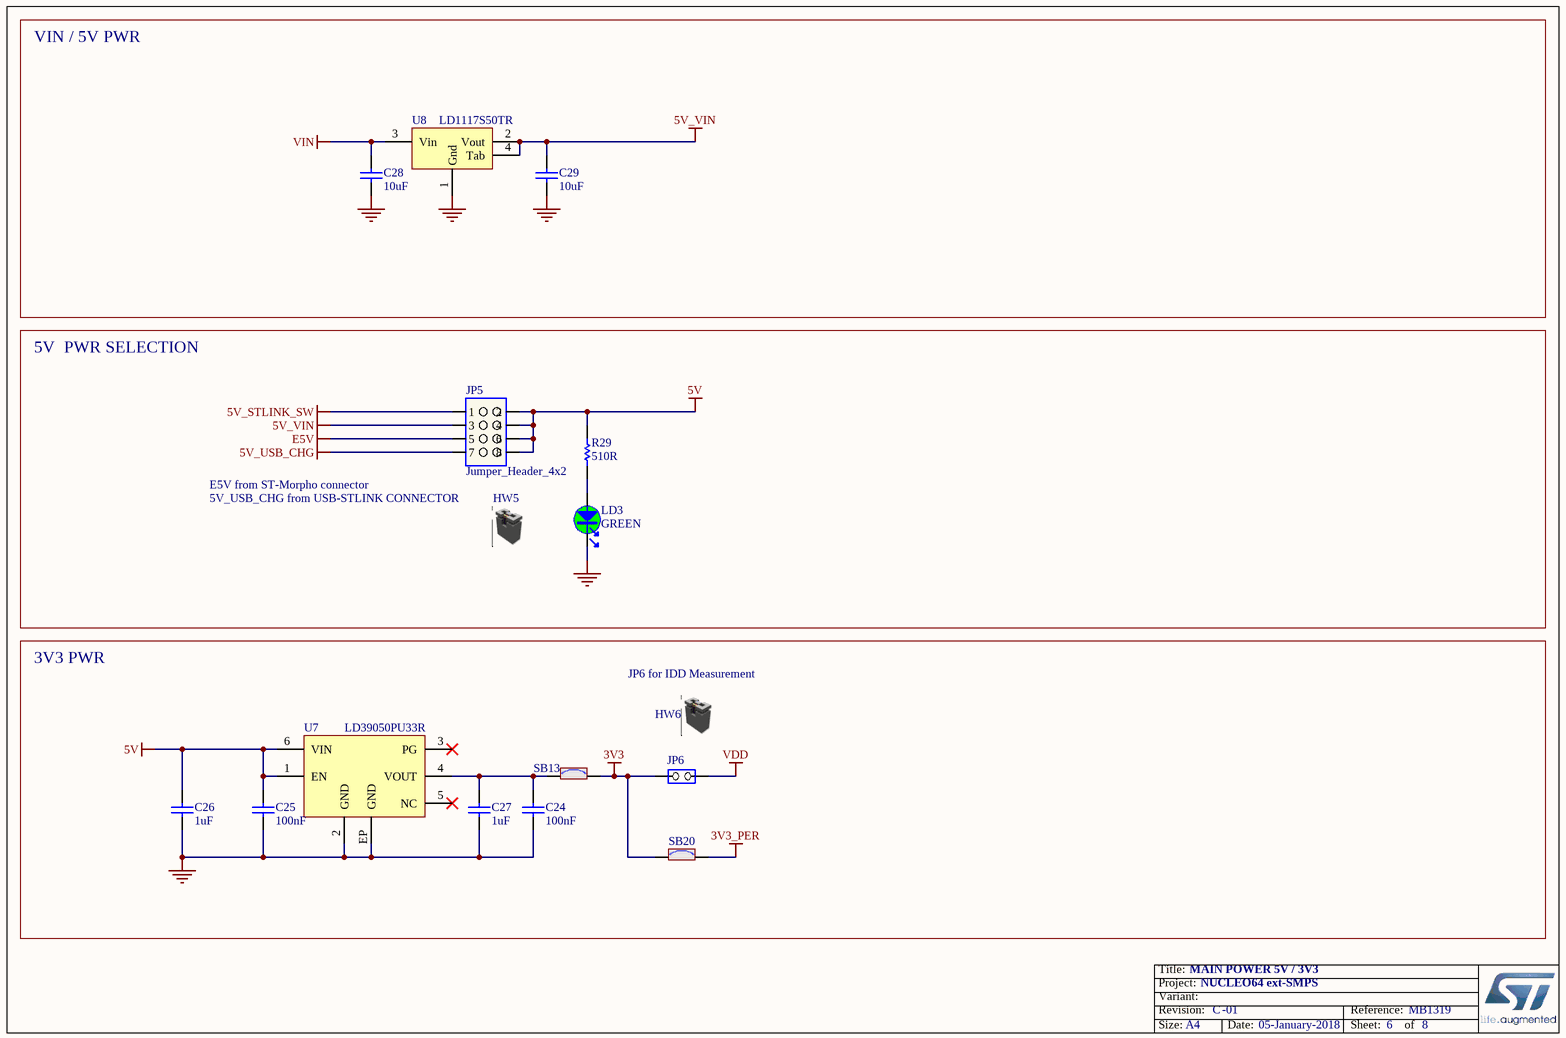
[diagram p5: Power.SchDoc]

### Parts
C24  value 100nF  [C0603]  (hidden comment: Capacitor)
C25  value 100nF  [C0603]  (hidden comment: Capacitor)
C26  value 1uF  [C0603]  (hidden comment: Capacitor)
C27  value 1uF  [C0603]  (hidden comment: Capacitor)
C28  value 10uF  [C0805]  (hidden comment: Capacitor)
C29  value 10uF  [C0805]  (hidden comment: Capacitor)
HW5  Shunt 2.54mm  [N/A]  (value not drawn)  (mechanical)
HW6  Shunt 2.54mm  [N/A]  (value not drawn)  (mechanical)
JP5  value Jumper_Header_4x2  [CON_SAMTEC_TSW-104-07-X-D]  (hidden comment: Jumper_Header 4x2)
JP6  Jumper Header 2x1  [CON_SAMTEC_TSW-102-07-G-S]  (value not drawn)
LD3  value GREEN  [LED_0603_GREEN]  (hidden comment: LED_green)
R29  value 510R  [R0603]  (hidden comment: Resistor)
SB13  SB_ON  [SOLDER-BRIDGE_R0603-0R]  (value not drawn)
SB20  SB_ON  [SOLDER-BRIDGE_R0603-0R]  (value not drawn)
U7  LD39050PU33R  [ICC_DFN6-EPAD_3X3_P095]
U8  LD1117S50TR  [REG_SOT223-TAB]

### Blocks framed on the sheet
VIN / 5V PWR: C28 C29 U8
5V  PWR SELECTION: HW5 JP5 LD3 R29
3V3 PWR: C24-C27 HW6 JP6 SB13 SB20 U7

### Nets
3V3: JP6.1(COMMON) SB13.2 SB20.1
3V3_PER: SB20.2
5V: C25.2 C26.2 JP5.2 JP5.4 JP5.6 JP5.8 R29.2 U7.1(EN) U7.6(VIN)
5V_STLINK_SW: JP5.1
5V_USB_CHG: JP5.7
5V_VIN: C29.2 JP5.3 U8.2(Vout) U8.4(Tab)
E5V: JP5.5
GND: C24.1 C25.1 C26.1 C27.1 C28.1 C29.1 LD3.2 U7.2(GND) U7.EP(GND) U8.1(Gnd)
VDD: JP6.2(NO)
VIN: C28.2 U8.3(Vin)
NetC24_2: C24.2 C27.2 SB13.1 U7.4(VOUT)
NetLD3_1: LD3.1 R29.1

Not connected (* = marked no-connect by the designer): U7 3(PG)* 5(NC)*

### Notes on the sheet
- E5V from ST-Morpho connector
- 5V_USB_CHG from USB-STLINK CONNECTOR
- (near HW6) JP6 for IDD Measurement

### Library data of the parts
C24 C25 = MCD-00237: as C21 on sheet STM32_microcontroller_IOs
C26 C27 = MCD-00238: as C30 on sheet STM32_microcontroller_power
C28 C29 = MCD-00014: Capacitor,10uF,25V,X5R,10%,0805; Manufacturer_Part_Number: C'0805KRX5R8BB106; Manufacturer: YAGEO; Provided_By: Subcon; Initial_Board_Reference: mb1274
HW5 HW6 = MCD-00043: SHUNT 2.54mm BLACK; Manufacturer_Part_Number: SNT-100-BK-G; Manufacturer: SAMTEC; Provided_By: Subcon
JP5 = MCD-00633: Header, 4x2, 2,54mm, VR, TH, Height 5.84mm/2.54mm; Part_Type: Connector; Manufacturer_Part_Number: TSW-104-07-x-D; Manufacturer: SAMTEC; Provided_By: Subcon; Initial_Board_Reference: mb1319
JP6 = MCD-00045: Header, 2x1, 2,54mm, VR, TH, Height 5.84mm/2.54mm; Manufacturer_Part_Number: TSW-102-07-x-S; Manufacturer: SAMTEC; Part_Type: Connector; Value: Jumper_Header_2x1; Provided_By: Subcon; Initial_Board_Reference: mb1274
LD3 = MCD-00050: as LD4 on sheet Arduino_extension_connectors
R29 = MCD-00225: as R34 on sheet Arduino_extension_connectors
SB13 SB20 = MCD-00071: as SB16 on sheet STM32_microcontroller_IOs
U7 = MCD-00215: Low quiescent current and low noise voltage regulators; Manufacturer: STMICROELECTRONICS; Part_Type: IC; ECCN_US: EAR99; ECCN_EU: NEC; Provided_By: Subcon; Initial_Board_Reference: mb1319
U8 = MCD-00088: IC REG LDO 5V 0.8A SOT223; Manufacturer: STMICROELECTRONICS; ECCN_US: EAR99; ECCN_EU: NEC; Provided_By: Subcon; Initial_Board_Reference: mb1274

## Sheet Power SMPS.SchDoc: STM32 Power SMPS
size A3; Date: Not used; ApprovedBy: Not used; CheckedBy: Not used; Author: Not used; CompanyName: STMicroelectronics; DrawnBy: Not used; Engineer: Not used; Organization: Not used; Address1: Not used; Address2: Not used; Address3: Not used; Address4: Not used; DocumentNumber: 7; Revision: Not used; SheetNumber: 7; SheetTotal: 8
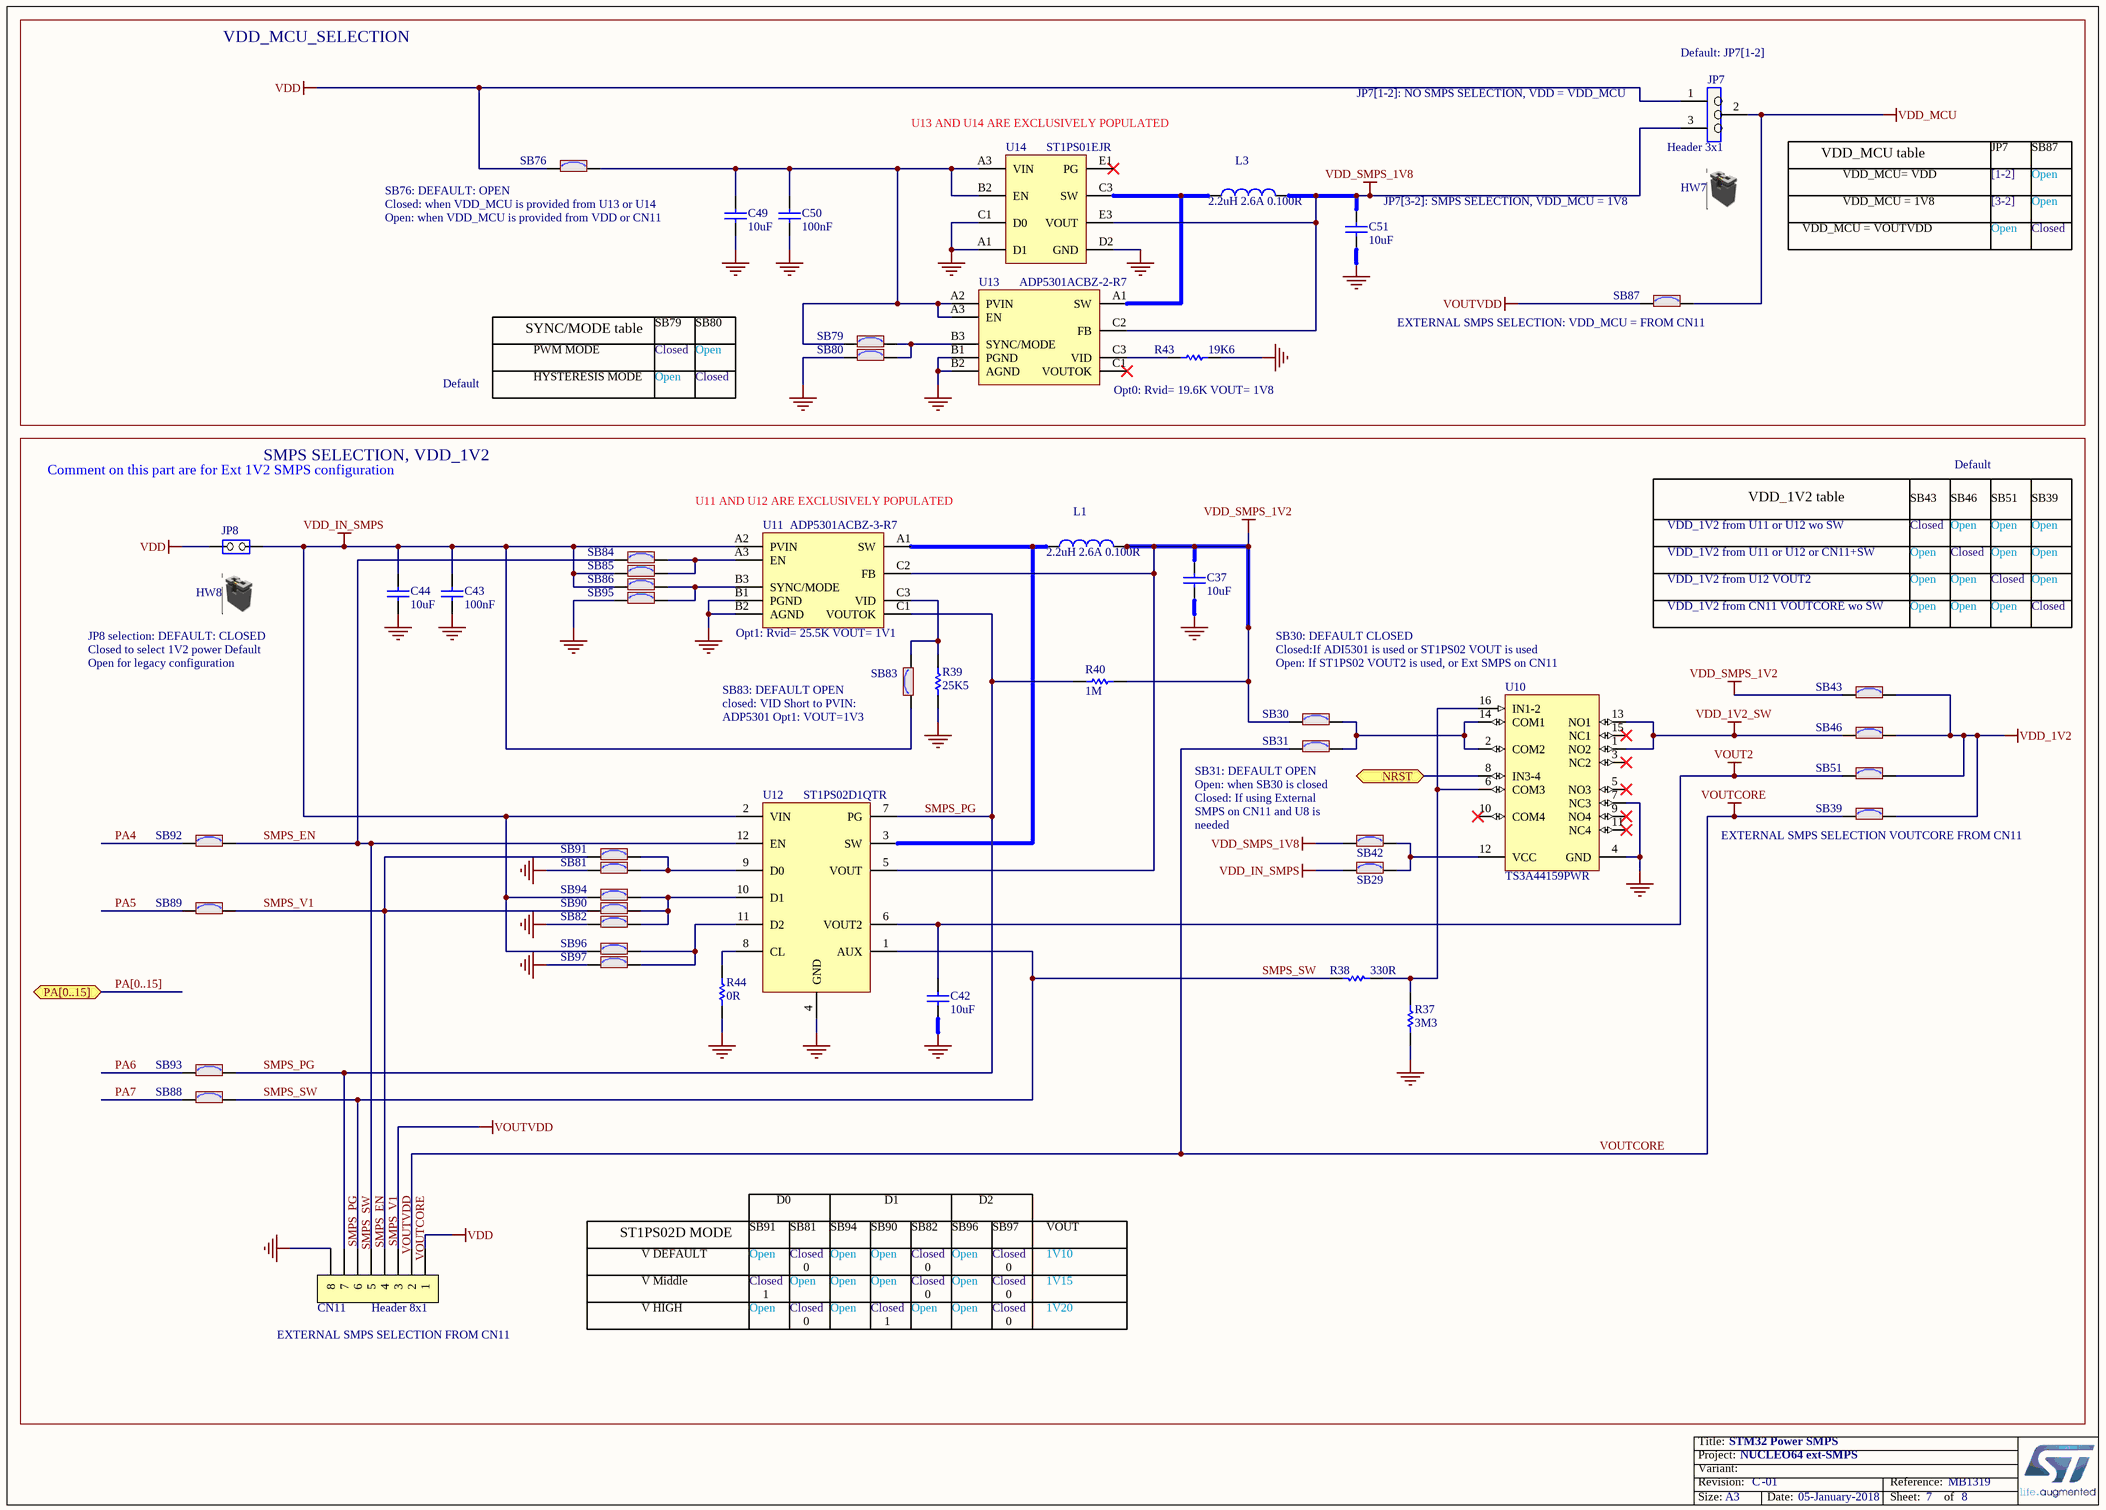
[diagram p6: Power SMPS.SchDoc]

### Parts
C37  value 10uF  [C0603]  (hidden comment: Capacitor)
C42  value 10uF  [C0603]  (hidden comment: Capacitor)
C43  value 100nF  [C0603]  (hidden comment: Capacitor)
C44  value 10uF  [C0603]  (hidden comment: Capacitor)
C49  value 10uF  [C0603]  (hidden comment: Capacitor)
C50  value 100nF  [C0603]  (hidden comment: Capacitor)
C51  value 10uF  [C0603]  (hidden comment: Capacitor)
CN11  Header 8x1  [CON_SAMTEC_TSW-108-07-X-S]
HW7  Shunt 2.54mm  [N/A]  (value not drawn)  (mechanical)
HW8  Shunt 2.54mm  [N/A]  (value not drawn)  (mechanical)
JP7  value Header 3x1  [CON_SAMTEC_TSW-103-07-F-S]  (hidden comment: Jumper_Header 3x1)
JP8  Jumper Header 2x1  [CON_SAMTEC_TSW-102-07-G-S]  (value not drawn)
L1  value 2.2uH 2.6A 0.100R  [IND_TDK_VLS252010HBX-1]  (hidden comment: Inductor)
L3  value 2.2uH 2.6A 0.100R  [IND_TDK_VLS252010HBX-1]  (hidden comment: Inductor)
R37  value 3M3  [R0603]  (hidden comment: Resistor)
R38  value 330R  [R0603]  (hidden comment: Resistor)
R39  value 25K5  [R0603]  (hidden comment: Resistor)
R40  value 1M  [R0603]  (hidden comment: Resistor)
R43  value 19K6  [R0603]  (hidden comment: Resistor)
R44  value 0R  [R0603]  (hidden comment: Resistor)
SB29  SB_ON  [SOLDER-BRIDGE_R0603-0R]  (value not drawn)
SB30  SB_ON  [SOLDER-BRIDGE_R0603-0R]  (value not drawn)
SB31  SB_ON  [SOLDER-BRIDGE_R0603-0R]  (value not drawn)
SB39  SB_ON  [SOLDER-BRIDGE_R0603-0R]  (value not drawn)
SB42  SB_ON  [SOLDER-BRIDGE_R0603-0R]  (value not drawn)
SB43  SB_ON  [SOLDER-BRIDGE_R0603-0R]  (value not drawn)
SB46  SB_ON  [SOLDER-BRIDGE_R0603-0R]  (value not drawn)
SB51  SB_ON  [SOLDER-BRIDGE_R0603-0R]  (value not drawn)
SB76  SB_ON  [SOLDER-BRIDGE_R0603-0R]  (value not drawn)
SB79  SB_ON  [SOLDER-BRIDGE_R0603-0R]  (value not drawn)
SB80  SB_ON  [SOLDER-BRIDGE_R0603-0R]  (value not drawn)
SB81  SB_ON  [SOLDER-BRIDGE_R0603-0R]  (value not drawn)
SB82  SB_ON  [SOLDER-BRIDGE_R0603-0R]  (value not drawn)
SB83  SB_ON  [SOLDER-BRIDGE_R0603-0R]  (value not drawn)
SB84  SB_ON  [SOLDER-BRIDGE_R0603-0R]  (value not drawn)
SB85  SB_ON  [SOLDER-BRIDGE_R0603-0R]  (value not drawn)
SB86  SB_ON  [SOLDER-BRIDGE_R0603-0R]  (value not drawn)
SB87  SB_ON  [SOLDER-BRIDGE_R0603-0R]  (value not drawn)
SB88  SB_ON  [SOLDER-BRIDGE_R0603-0R]  (value not drawn)
SB89  SB_ON  [SOLDER-BRIDGE_R0603-0R]  (value not drawn)
SB90  SB_ON  [SOLDER-BRIDGE_R0603-0R]  (value not drawn)
SB91  SB_ON  [SOLDER-BRIDGE_R0603-0R]  (value not drawn)
SB92  SB_ON  [SOLDER-BRIDGE_R0603-0R]  (value not drawn)
SB93  SB_ON  [SOLDER-BRIDGE_R0603-0R]  (value not drawn)
SB94  SB_ON  [SOLDER-BRIDGE_R0603-0R]  (value not drawn)
SB95  SB_ON  [SOLDER-BRIDGE_R0603-0R]  (value not drawn)
SB96  SB_ON  [SOLDER-BRIDGE_R0603-0R]  (value not drawn)
SB97  SB_ON  [SOLDER-BRIDGE_R0603-0R]  (value not drawn)
U10  TS3A44159PWR  [ICC_TSSOP16_5P1X4P5_P065]
U11  value ADP5301ACBZ-3-R7  [ICC_WLCSP9_1P65X1P87_P050]  (hidden comment: ADP5301)
U12  ST1PS02D1QTR  [ICC_TQFN12_2X1P7_P040]
U13  value ADP5301ACBZ-2-R7  [ICC_WLCSP9_1P65X1P87_P050]  (hidden comment: ADP5301)
U14  ST1PS01EJR  [ICC_FLIP-CHIP-BGA8_1P11X1P41_P040]

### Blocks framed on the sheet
VDD_MCU_SELECTION: C49-C51 HW7 JP7 L3 R43 SB76 SB79 SB80 SB87 U13 U14
SMPS SELECTION, VDD_1V2: C37 C42-C44 CN11 HW8 JP8 L1 R37-R40 R44 SB29-SB31 SB39 SB42 SB43 SB46 SB51 SB81-SB86 SB88-SB97 U10-U12

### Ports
NRST, PA[0..15] (bidir)

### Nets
GND: C37.1 C42.1 C43.1 C44.1 C49.1 C50.1 C51.1 CN11.8 R37.1 R39.1 R43.2 R44.1 SB80.1 SB81.1 SB82.1 SB95.1 SB97.1 U10.4(GND) U10.7(NC3) U11.B1(PGND) U11.B2(AGND) U12.4(GND) U13.B1(PGND) U13.B2(AGND) U14.A1(D1) U14.C1(D0) U14.D2(GND)
VDD: CN11.1 JP7.1 JP8.1(COMMON) SB76.1
VDD_1V2: SB39.2 SB43.2 SB46.2 SB51.2
VDD_1V2_SW: SB46.1 U10.1(NO2) U10.13(NO1)
VDD_IN_SMPS: C43.2 C44.2 JP8.2(NO) SB29.1 SB83.1 SB85.1 SB86.1 SB94.1 SB96.1 U11.A2(PVIN) U12.2(VIN)
VDD_MCU: JP7.2 SB87.2
VDD_SMPS_1V2: C37.2 L1.2 R40.2 SB30.1 SB43.1 U11.C2(FB) U12.5(VOUT)
VDD_SMPS_1V8: C51.2 JP7.3 L3.2 SB42.1 U13.C2(FB) U14.E3(VOUT)
VOUT2: C42.2 SB51.1 U12.6(VOUT2)
VOUTCORE: CN11.2 SB31.1 SB39.1
VOUTVDD: CN11.3 SB87.1
NRST: U10.8(IN3-4) ; port NRST
PA4: SB92.2
PA5: SB89.2
PA6: SB93.2
PA7: SB88.2
SMPS_EN: CN11.5 SB84.1 SB92.1 U12.12(EN)
SMPS_PG: CN11.7 R40.1 SB93.1 U11.C1(VOUTOK) U12.7(PG)
SMPS_SW: CN11.6 R38.2 SB88.1 U12.1(AUX)
SMPS_V1: CN11.4 SB89.1 SB90.1 SB91.1
NetC49_2: C49.2 C50.2 SB76.2 SB79.1 U13.A2(PVIN) U13.A3(EN) U14.A3(VIN) U14.B2(EN)
NetL1_1: L1.1 U11.A1(SW) U12.3(SW)
NetL3_1: L3.1 U13.A1(SW) U14.C3(SW)
NetR37_2: R37.2 R38.1 U10.6(COM3) U10.16(IN1-2)
NetR39_2: R39.2 SB83.2 U11.C3(VID)
NetR43_1: R43.1 U13.C3(VID)
NetR44_2: R44.2 U12.8(CL)
NetSB29_2: SB29.2 SB42.2 U10.12(VCC)
NetSB30_2: SB30.2 SB31.2 U10.2(COM2) U10.14(COM1)
NetSB79_2: SB79.2 SB80.2 U13.B3(SYNC/MODE)
NetSB81_2: SB81.2 SB91.2 U12.9(D0)
NetSB82_2: SB82.2 SB90.2 SB94.2 U12.10(D1)
NetSB84_2: SB84.2 SB85.2 U11.A3(EN)
NetSB86_2: SB86.2 SB95.2 U11.B3(SYNC/MODE)
NetSB96_2: SB96.2 SB97.2 U12.11(D2)

Not connected (* = marked no-connect by the designer): U10 3(NC2)* 5(NO3)* 9(NO4)* 10(COM4)* 11(NC4)* 15(NC1)*; U13 C1(VOUTOK)*; U14 E1(PG)*

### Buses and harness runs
bus PA[0..15] = port PA[0..15]

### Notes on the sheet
- JP7[1-2]: NO SMPS SELECTION, VDD = VDD_MCU
- (near JP7) Default: JP7[1-2]
- (near U14) U13 AND U14 ARE EXCLUSIVELY POPULATED
- VDD_MCU table
- VDD_MCU= VDD
- JP7
- [1-2]
- SB87
- Open
- (near SB76) SB76: DEFAULT: OPEN
  Closed: when VDD_MCU is provided from U13 or U14
  Open: when VDD_MCU is provided from VDD or CN11
- (near C51) JP7[3-2]: SMPS SELECTION, VDD_MCU = 1V8
- VDD_MCU = VOUTVDD
- VDD_MCU = 1V8
- [3-2]
- Closed
- SYNC/MODE table
- PWM MODE
- HYSTERESIS MODE
- SB79
- SB80
- (near SB87) EXTERNAL SMPS SELECTION: VDD_MCU = FROM CN11
- Default
- Opt0: Rvid= 19.6K VOUT= 1V8
- Comment on this part are for Ext 1V2 SMPS configuration
- (near U11) U11 AND U12 ARE EXCLUSIVELY POPULATED
- VDD_1V2 table
- SB43
- SB46
- SB51
- SB39
- VDD_1V2 from U11 or U12 wo SW
- VDD_1V2 from U11 or U12 or CN11+SW
- VDD_1V2 from U12 VOUT2
- (near U11) Opt1: Rvid= 25.5K VOUT= 1V1
- VDD_1V2 from CN11 VOUTCORE wo SW
- JP8 selection: DEFAULT: CLOSED
  Closed to select 1V2 power Default
  Open for legacy configuration
- (near SB83) SB83: DEFAULT OPEN
  closed: VID Short to PVIN:
  ADP5301 Opt1: VOUT=1V3
- SB30: DEFAULT CLOSED
  Closed:If ADI5301 is used or ST1PS02 VOUT is used
  Open: If ST1PS02 VOUT2 is used, or Ext SMPS on CN11
- SB31: DEFAULT OPEN
  Open: when SB30 is closed
  Closed: If using External SMPS on CN11 and U8 is needed
- (near SB39) EXTERNAL SMPS SELECTION VOUTCORE FROM CN11
- ST1PS02D MODE
- V DEFAULT
- SB91
- D0
- SB81
- SB94
- SB90
- D1
- SB82
- SB96
- D2
- SB97
- VOUT
- 1V10
- V Middle
- V HIGH
- 1
- 0
- 1V15
- 1V20
- EXTERNAL SMPS SELECTION FROM CN11

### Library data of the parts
C37 C42 C44 C49 C51 = MCD-00243: Capacitor,10uF,6V3,X5R,10%,0603; Manufacturer_Part_Number: CC0603KRX5R5BB106; Manufacturer: YAGEO; Provided_By: Subcon; Initial_Board_Reference: mb1319
C43 C50 = MCD-00237: as C21 on sheet STM32_microcontroller_IOs
CN11 = MCD-00239: Header, 8x1, 2,54mm, VR, TH, Height 5.84mm/2.54mm; Manufacturer_Part_Number: TSW-108-07-x-S; Manufacturer: SAMTEC; Part_Type: Connector; Provided_By: Subcon; Initial_Board_Reference: mb1319
HW7 HW8 = MCD-00043: as HW5 on sheet Power
JP7 = MCD-00111: Header, 3x1, 2,54mm, VR, TH, Height 5.84mm/2.54mm; Manufacturer_Part_Number: TSW-103-07-F-S; Manufacturer: SAMTEC; Part_Type: Connector; ECCN_US: EAR99; ECCN_EU: NEC; Provided_By: Subcon; Initial_Board_Reference: mb1262
JP8 = MCD-00045: as JP6 on sheet Power
L1 L3 = MCD-00240: FIXED IND 2.2UH 2.6A 100 mOHM 20% SMD; Manufacturer_Part_Number: VLS252010HBX-2R2M-1; Manufacturer: TDK; Provided_By: Subcon; Initial_Board_Reference: mb1319
R37 = MCD-00241: Resistor,3M3,0603,1%,1/10W; Manufacturer_Part_Number: RC0603FR-073M3L; Manufacturer: YAGEO; Provided_By: Subcon; Initial_Board_Reference: mb1319
R38 = MCD-00197: Resistor,330R,0603,1%,1/10W; Manufacturer_Part_Number: RC0603FR-07330RL; Manufacturer: YAGEO; Provided_By: Subcon
R39 = MCD-00546: Resistor,25K5,0603,1%,1/10W; Manufacturer_Part_Number: RC0603FR-0725K5L; Manufacturer: YAGEO; Provided_By: Subcon
R40 = MCD-00257: Resistor,1M,0603,1%,1/10W; Manufacturer_Part_Number: RC0603FR-071ML; Manufacturer: YAGEO; Provided_By: Subcon; Initial_Board_Reference: mb1319
R43 = MCD-00242: Resistor,19K6,0603,1%,1/10W; Manufacturer_Part_Number: RC0603FR-0719K6L; Manufacturer: YAGEO; Provided_By: Subcon; Initial_Board_Reference: mb1319
R44 = MCD-00056: as R41 on sheet STM32_microcontroller_IOs
SB29-SB31 SB39 SB42 SB43 SB46 SB51 SB76 SB79-SB97 = MCD-00071: as SB16 on sheet STM32_microcontroller_IOs
U10 = MCD-00090: SPDT analog switch 4-Channel 2:1 bidirectional; Manufacturer: TEXAS INSTRUMENTS; Part_Type: IC; ECCN_US: EAR99; ECCN_EU: NEC; Provided_By: Subcon; Initial_Board_Reference: mb1274
U11 = MCD-00230: UL Step down regulator: Opt1; Part_Type: IC; Manufacturer: ANALOG DEVICES; Provided_By: SUBCO; Initial_Board_Reference: MB1319; Item Type: Item; Path: ws/MCD_ApplicationBoards/Lists/MCDPARTSdatabase
U12 = MCD-00229: 400mA Nano-Quiescent Step down converter with Aux switch; Manufacturer: STMICROELECTRONICS; Part_Type: IC; ECCN_US: EAR99; ECCN_EU: NEC; Provided_By: Subcon; Initial_Board_Reference: mb1319
U13 = MCD-00226: UL Step down regulator: Opt0; Manufacturer: ANALOG DEVICES; Part_Type: IC; ECCN_US: EAR99; ECCN_EU: NEC; Provided_By: Subcon; Initial_Board_Reference: mb1319
U14 = MCD-00228: 400mA Nano-Quiescent Step down converter; Manufacturer: STMICROELECTRONICS; Part_Type: IC; ECCN_US: EAR99; ECCN_EU: NEC; Provided_By: Subcon; Initial_Board_Reference: mb1319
